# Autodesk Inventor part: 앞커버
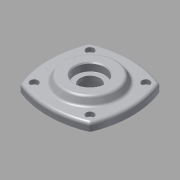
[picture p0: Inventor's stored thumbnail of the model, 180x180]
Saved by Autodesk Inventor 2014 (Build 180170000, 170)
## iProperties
Created: 2013-02
Part Number: 앞커버
Document SubType Name: Modeling
Designer: 한국산업디자인학원[gmhk.co.kr]
Density: 2.71 g/cm^3
Material: 알루미늄 6061
Mass: 206.617 g
Surface Area: 198.108 cm^2
Volume: 76.2425 cm^3
Appearance: 알루미늄 - 평지
Author: 한국산업디자인학원[gmhk.co.kr]
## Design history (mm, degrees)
sketch "스케치1"
  geometry: C1 r 30 at (0, 0) reference; A1 r 91.05 centre (0, -48.55) between (34.185, 35.839) and (-34.185, 35.839) reference; A2 r 91.05 centre (48.55, 0) between (-35.839, 34.185) and (-35.839, -34.185) reference; A3 r 3 centre (-33.058, 33.058) between (-34.185, 35.839) and (-35.839, 34.185) reference; A4 r 3 centre (33.058, 33.058) between (35.839, 34.185) and (34.185, 35.839) reference; A5 r 91.05 centre (-48.55, 0) between (35.839, -34.185) and (35.839, 34.185) reference; A6 r 3 centre (33.058, -33.058) between (34.185, -35.839) and (35.839, -34.185) reference; A7 r 91.05 centre (0, 48.55) between (-34.185, -35.839) and (34.185, -35.839) reference; A8 r 3 centre (-33.058, -33.058) between (-35.839, -34.185) and (-34.185, -35.839) reference; 1 further point
  node "참조1"
  node "참조2"
  node "참조3"
  node "참조4"
  node "참조5"
  node "참조6"
  node "참조7"
  node "참조8"
  node "참조9"
extrude "돌출1" new body sketch "스케치1" distance "d0" = 8; taper "d1" = 0 deg
sketch "스케치2"
  geometry: C1 r 30 at (0, 0); 1 further point
  constraints: 1 centre point, 1 coincident
  dimensions: "d2" = 60 diameter of C1
extrude "돌출2" join sketch "스케치2" distance "d3" = 7; taper "d4" = -30 deg
hole "구멍1" diameter "d7" = 20; stored, may be unused: countersink angle "d11" = 90 deg, drill point angle "d13" = 118 deg; dims "d5" = 10, "d6" = 10, "d8" = 6, "d9" = 30, "d10" = 8, "d12" = 20
sketch "스케치3"
  geometry: C1 r 1.621 at (28.284, 28.284) reference; C2 r 1.621 at (-28.284, 28.284) reference; C3 r 1.621 at (-28.284, -28.284) reference; C4 r 1.621 at (28.284, -28.284) reference; 1 further point
hole "구멍2" sketch "스케치3" at (28.284, 28.284), (28.284, -28.284), (-28.284, -28.284), (-28.284, 28.284) diameter "d14" = 4.5; stored, may be unused: countersink angle "d18" = 90 deg, drill point angle "d20" = 118 deg; dims "d15" = 6, "d16" = 8, "d17" = 4.4, "d19" = 20
extrude "돌출3" join sketch "스케치1" distance "d21" = 12; taper "d22" = 0 deg
hole "구멍3" diameter "d25" = 30; stored, may be unused: countersink angle "d29" = 90 deg, drill point angle "d31" = 0 deg; dims "d23" = 10, "d24" = 10, "d26" = 6, "d27" = 40, "d28" = 12, "d30" = 15
fillet "모깎기1" dims "d32" = 3, "d33" = 0.3
chamfer "모따기1" distance "d34" = 1; stored, may be unused: second distance "d35" = 2, angle "d36" = 45 deg
node "솔리드1"
node "참조10"
node "참조11"
node "참조12"
node "참조13"
